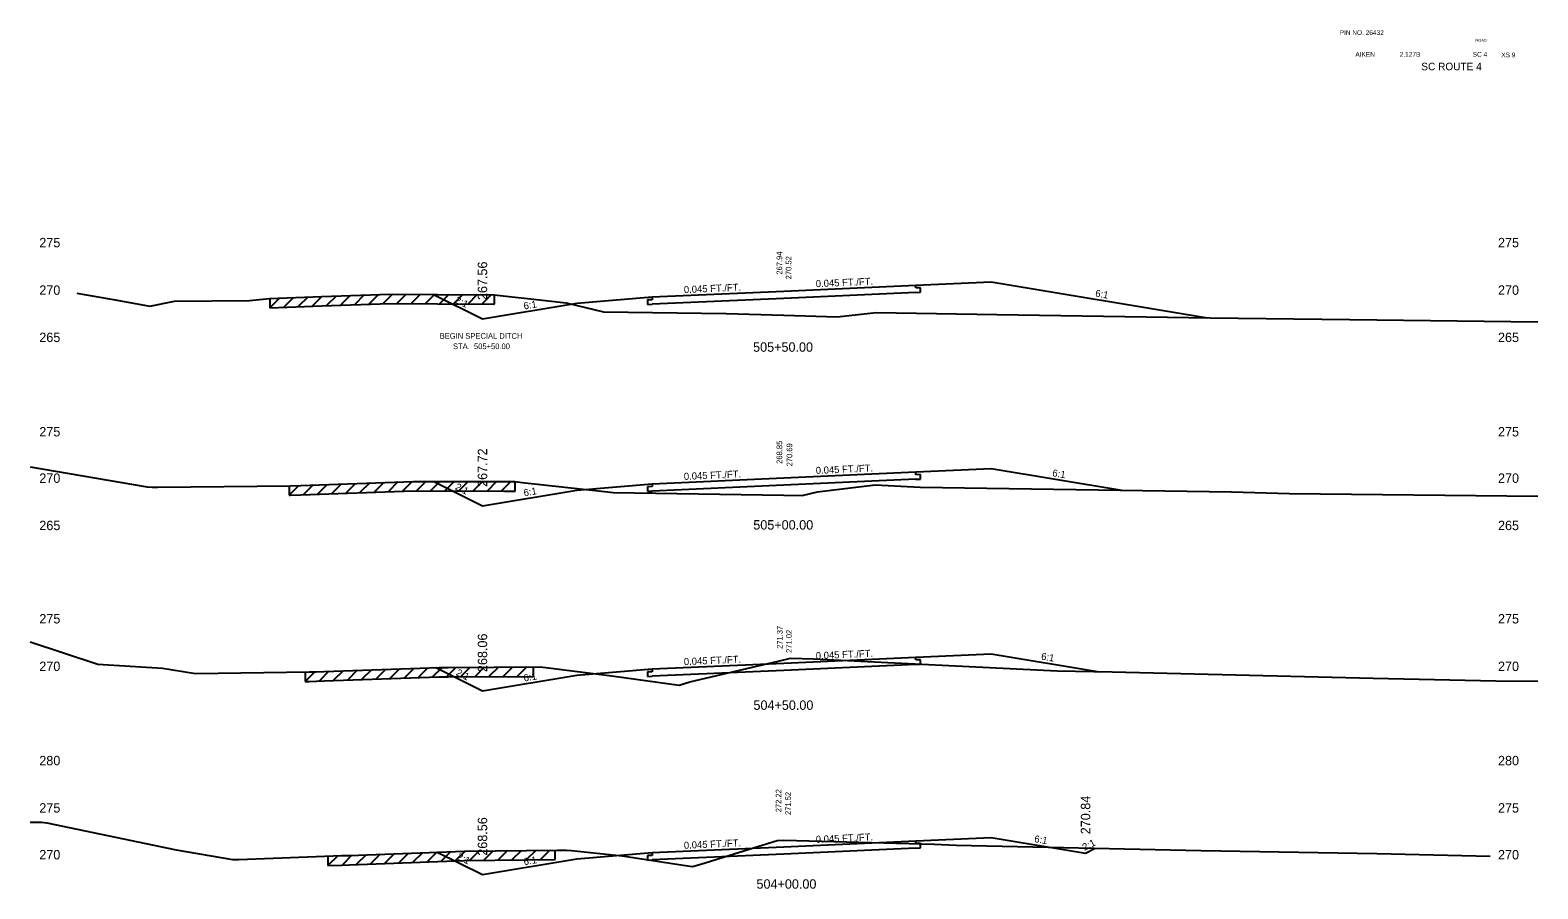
# Model space of a CAD drawing. Extents: x 883 to 1160, y 1002 to 4323.
# Drawn here: x 1000 to 1160, y 1932 to 2023.2 of the extents above; entities that cross this region are included whole.
import ezdxf

# ---------------------------------------------------------------- set-up
doc = ezdxf.new("R2010")
doc.units = 0
for name, color, linetype in [('Level 1', 7, 'Continuous'), ('Level 10', 7, 'Continuous'), ('Level 11', 7, 'Continuous'), ('Level 12', 7, 'Continuous'), ('Level 3', 7, 'Continuous'), ('Level 32', 7, 'Continuous'), ('Level 33', 7, 'Continuous'), ('Level 59', 7, 'Continuous'), ('Level 6', 7, 'Continuous'), ('Level 60', 7, 'Continuous'), ('Level 61', 7, 'Continuous'), ('Level 7', 7, 'Continuous')]:
    doc.layers.add(name, color=color, linetype=linetype)

msp = doc.modelspace()

# ---------------------------------------------------------------- linework, layer by layer
at = {"layer": 'Level 11'}
for p, q in [((1094, 1995.85), (1094, 1996.15)), ((1094.5, 1995.87), (1094, 1995.85)), ((1094, 1995.37), (1094.5, 1995.39)), ((1094.5, 1995.39), (1094.5, 1995.87)), ((1066, 1994.59), (1065.5, 1994.57)), ((1065.5, 1994.57), (1065.5, 1994.09)), ((1065.5, 1994.09), (1066, 1994.11)), ((1066, 1994.89), (1066, 1994.59)), ((1094, 1976.02), (1094, 1976.32)), ((1094.5, 1976.04), (1094, 1976.02)), ((1094.5, 1975.56), (1094.5, 1976.04)), ((1066, 1974.76), (1065.5, 1974.74)), ((1065.5, 1974.74), (1065.5, 1974.26)), ((1066, 1975.06), (1066, 1974.76)), ((1094, 1975.54), (1094.5, 1975.56)), ((1065.5, 1974.26), (1066, 1974.28)), ((1066, 1955.39), (1066, 1955.09)), ((1094, 1956.35), (1094, 1956.65)), ((1094.5, 1956.37), (1094, 1956.35)), ((1094, 1955.87), (1094.5, 1955.89)), ((1094.5, 1955.89), (1094.5, 1956.37)), ((1066, 1955.09), (1065.5, 1955.07)), ((1065.5, 1955.07), (1065.5, 1954.59)), ((1065.5, 1954.59), (1066, 1954.61)), ((1094, 1936.85), (1094, 1937.15)), ((1094.5, 1936.87), (1094, 1936.85)), ((1094, 1936.37), (1094.5, 1936.39)), ((1094.5, 1936.39), (1094.5, 1936.87)), ((1066, 1935.59), (1065.5, 1935.57)), ((1065.5, 1935.57), (1065.5, 1935.09)), ((1065.5, 1935.09), (1066, 1935.11)), ((1066, 1935.89), (1066, 1935.59))]:
    msp.add_line(p, q, dxfattribs=at)
at = {"layer": 'Level 12'}
for p, q in [((1094, 1995.37), (1080, 1994.74)), ((1080, 1994.74), (1066, 1994.11)), ((1080, 1974.91), (1066, 1974.28)), ((1094, 1975.54), (1080, 1974.91)), ((1080, 1955.24), (1066, 1954.61)), ((1094, 1955.87), (1080, 1955.24)), ((1094, 1936.37), (1080, 1935.74)), ((1080, 1935.74), (1066, 1935.11))]:
    msp.add_line(p, q, dxfattribs=at)
at = {"layer": 'Level 59'}
for p, q in [((1066, 1994.89), (1080, 1995.52)), ((1080, 1995.52), (1094, 1996.15)), ((1080, 1975.69), (1094, 1976.32)), ((1066, 1975.06), (1080, 1975.69)), ((1066, 1955.39), (1080, 1956.02)), ((1080, 1956.02), (1094, 1956.65)), ((1066, 1935.89), (1080, 1936.52)), ((1080, 1936.52), (1094, 1937.15))]:
    msp.add_line(p, q, dxfattribs=at)
at = {"layer": 'Level 6'}
for p, q in [((1094, 1996.15), (1102, 1996.51)), ((1058, 1994.22), (1066, 1994.89)), ((1094, 1976.32), (1102, 1976.68)), ((1058, 1974.39), (1066, 1975.06)), ((1094, 1956.65), (1102, 1957.01)), ((1058, 1954.72), (1066, 1955.39)), ((1094, 1937.15), (1102, 1937.51)), ((1058, 1935.22), (1066, 1935.89))]:
    msp.add_line(p, q, dxfattribs=at)
at = {"layer": 'Level 60'}
for p, q in [((1004.95, 1995.29), (1009.02, 1994.59)), ((1009.02, 1994.59), (1012.7, 1993.9)), ((1012.7, 1993.9), (1015.32, 1994.44)), ((1015.32, 1994.44), (1023.28, 1994.51)), ((1023.28, 1994.51), (1025.39, 1994.73)), ((1025.39, 1994.73), (1030.97, 1994.94)), ((1030.97, 1994.94), (1038.17, 1995.2)), ((1038.17, 1995.2), (1043.24, 1995.15)), ((1043.24, 1995.15), (1049.23, 1995.13)), ((1049.23, 1995.13), (1054.7, 1994.53)), ((1054.7, 1994.53), (1056.87, 1994.25)), ((1056.87, 1994.25), (1060.86, 1993.31)), ((1060.86, 1993.31), (1073.88, 1993.13)), ((1073.88, 1993.13), (1080, 1992.94)), ((1080, 1992.94), (1085.64, 1992.77)), ((1085.64, 1992.77), (1089.77, 1993.24)), ((1089.77, 1993.24), (1102.57, 1993.04)), ((1102.57, 1993.04), (1125.21, 1992.68)), ((1125.21, 1992.68), (1140.06, 1992.48)), ((1140.06, 1992.48), (1160, 1992.25)), ((1000, 1976.86), (1012.41, 1974.74)), ((1012.41, 1974.74), (1012.95, 1974.7)), ((1012.95, 1974.7), (1013.55, 1974.71)), ((1013.55, 1974.71), (1027.58, 1974.84)), ((1027.58, 1974.84), (1028.71, 1974.88)), ((1028.71, 1974.88), (1040.66, 1975.31)), ((1040.66, 1975.31), (1050.35, 1975.28)), ((1050.35, 1975.28), (1051.45, 1975.28)), ((1051.45, 1975.28), (1052.2, 1975.19)), ((1052.2, 1975.19), (1060.94, 1974.23)), ((1083.57, 1974.21), (1089.69, 1974.93)), ((1089.69, 1974.93), (1094.46, 1974.7)), ((1094.46, 1974.7), (1127.49, 1974.19)), ((1060.94, 1974.23), (1061.86, 1974.11)), ((1061.86, 1974.11), (1080, 1973.85)), ((1080, 1973.85), (1081.93, 1973.82)), ((1081.93, 1973.82), (1083.57, 1974.21)), ((1127.49, 1974.19), (1133.63, 1974.03)), ((1133.63, 1974.03), (1160, 1973.73)), ((1000, 1958.28), (1007.17, 1955.91)), ((1007.17, 1955.91), (1014.06, 1955.48)), ((1014.06, 1955.48), (1017.55, 1954.92)), ((1031.2, 1955.13), (1043.41, 1955.54)), ((1043.41, 1955.54), (1044.35, 1955.55)), ((1044.35, 1955.55), (1054.14, 1955.61)), ((1054.14, 1955.61), (1054.74, 1955.54)), ((1054.74, 1955.54), (1061.18, 1954.73)), ((1070, 1954.03), (1080, 1956.37)), ((1080, 1956.37), (1080.68, 1956.53)), ((1080.68, 1956.53), (1083.14, 1956.46)), ((1083.14, 1956.46), (1108.98, 1955.19)), ((1017.55, 1954.92), (1029.61, 1955.07)), ((1029.61, 1955.07), (1030.35, 1955.1)), ((1030.35, 1955.1), (1031.2, 1955.13)), ((1061.18, 1954.73), (1061.98, 1954.61)), ((1061.98, 1954.61), (1068.87, 1953.68)), ((1068.87, 1953.68), (1070, 1954.03)), ((1108.98, 1955.19), (1114.84, 1955.07)), ((1114.84, 1955.07), (1142.54, 1954.42)), ((1142.54, 1954.42), (1155.53, 1954.12)), ((1155.53, 1954.12), (1160, 1954.11)), ((1000, 1939.12), (1001.19, 1939.12)), ((1001.19, 1939.12), (1001.76, 1939.07)), ((1001.76, 1939.07), (1015.49, 1936.19)), ((1015.49, 1936.19), (1021.48, 1935.15)), ((1033.89, 1935.6), (1046.09, 1936.06)), ((1046.09, 1936.06), (1055.98, 1936.15)), ((1055.98, 1936.15), (1056.91, 1936.16)), ((1056.91, 1936.16), (1057.44, 1936.11)), ((1057.44, 1936.11), (1062.82, 1935.54)), ((1071.18, 1934.66), (1079.26, 1937.16)), ((1079.26, 1937.16), (1080, 1937.22)), ((1080, 1937.22), (1095.92, 1936.8)), ((1095.92, 1936.8), (1098.27, 1936.67)), ((1098.27, 1936.67), (1124.27, 1936.11)), ((1124.27, 1936.11), (1142.92, 1935.8)), ((1021.48, 1935.15), (1022.13, 1935.15)), ((1022.13, 1935.15), (1033.06, 1935.57)), ((1033.06, 1935.57), (1033.89, 1935.6)), ((1062.82, 1935.54), (1069.55, 1934.52)), ((1069.55, 1934.52), (1070.3, 1934.43)), ((1070.3, 1934.43), (1071.18, 1934.66)), ((1142.92, 1935.8), (1154.93, 1935.53))]:
    msp.add_line(p, q, dxfattribs=at)
at = {"layer": 'Level 61'}
for p, q in [((1026.46, 1994.77), (1025.42, 1993.73)), ((1025.42, 1994.73), (1025.42, 1993.73)), ((1025.42, 1993.73), (1030.97, 1993.94)), ((1027.96, 1994.83), (1026.92, 1993.79)), ((1029.46, 1994.88), (1028.42, 1993.84)), ((1030.96, 1994.94), (1029.92, 1993.9)), ((1030.97, 1993.94), (1038.17, 1994.2)), ((1032.46, 1994.99), (1031.42, 1993.95)), ((1033.96, 1995.04), (1032.93, 1994.01)), ((1035.46, 1995.1), (1034.43, 1994.06)), ((1036.97, 1995.15), (1035.93, 1994.12)), ((1038.45, 1995.19), (1037.43, 1994.17)), ((1038.17, 1994.2), (1043.24, 1994.15)), ((1039.92, 1995.18), (1038.93, 1994.19)), ((1041.42, 1995.17), (1040.43, 1994.18)), ((1042.92, 1995.15), (1041.93, 1994.16)), ((1043.24, 1994.15), (1049.23, 1994.13)), ((1044.43, 1995.15), (1043.43, 1994.15)), ((1045.93, 1995.14), (1044.93, 1994.15)), ((1047.43, 1995.14), (1046.43, 1994.14)), ((1048.93, 1995.13), (1047.94, 1994.13)), ((1049.23, 1994.13), (1049.28, 1994.13)), ((1049.28, 1994.13), (1049.28, 1995.13)), ((1028.52, 1974.87), (1027.49, 1973.84)), ((1027.49, 1974.84), (1027.49, 1973.84)), ((1030.03, 1974.93), (1028.99, 1973.89)), ((1031.53, 1974.98), (1030.49, 1973.94)), ((1033.03, 1975.03), (1031.99, 1974)), ((1034.53, 1975.09), (1033.49, 1974.05)), ((1036.03, 1975.14), (1034.99, 1974.11)), ((1037.53, 1975.2), (1036.49, 1974.16)), ((1039.03, 1975.25), (1038, 1974.21)), ((1040.53, 1975.31), (1039.5, 1974.27)), ((1041.99, 1975.31), (1041, 1974.31)), ((1043.49, 1975.3), (1042.5, 1974.3)), ((1044.99, 1975.29), (1044, 1974.3)), ((1046.49, 1975.29), (1045.5, 1974.29)), ((1048, 1975.28), (1047, 1974.29)), ((1049.5, 1975.28), (1048.5, 1974.28)), ((1051, 1975.28), (1050, 1974.28)), ((1051.47, 1974.28), (1051.47, 1975.28)), ((1027.49, 1973.84), (1027.58, 1973.84)), ((1027.58, 1973.84), (1028.71, 1973.88)), ((1028.71, 1973.88), (1040.66, 1974.31)), ((1040.66, 1974.31), (1050.35, 1974.28)), ((1050.35, 1974.28), (1051.45, 1974.28)), ((1051.45, 1974.28), (1051.47, 1974.28)), ((1034.71, 1955.25), (1033.67, 1954.21)), ((1036.21, 1955.3), (1035.18, 1954.27)), ((1037.71, 1955.35), (1036.68, 1954.32)), ((1039.21, 1955.4), (1038.18, 1954.37)), ((1040.72, 1955.45), (1039.68, 1954.42)), ((1042.22, 1955.5), (1041.18, 1954.47)), ((1043.71, 1955.55), (1042.68, 1954.52)), ((1045.19, 1955.56), (1044.18, 1954.55)), ((1046.69, 1955.57), (1045.68, 1954.56)), ((1048.19, 1955.57), (1047.19, 1954.57)), ((1049.69, 1955.58), (1048.69, 1954.58)), ((1051.19, 1955.59), (1050.19, 1954.58)), ((1052.7, 1955.6), (1051.69, 1954.59)), ((1053.4, 1954.6), (1053.4, 1955.6)), ((1030.2, 1955.09), (1029.17, 1954.07)), ((1029.17, 1955.07), (1029.17, 1954.07)), ((1029.17, 1954.07), (1029.61, 1954.07)), ((1029.61, 1954.07), (1030.35, 1954.1)), ((1030.35, 1954.1), (1031.2, 1954.13)), ((1031.71, 1955.15), (1030.67, 1954.11)), ((1031.2, 1954.13), (1043.41, 1954.54)), ((1033.21, 1955.2), (1032.17, 1954.16)), ((1043.41, 1954.54), (1044.35, 1954.55)), ((1044.35, 1954.55), (1053.4, 1954.6)), ((1044.66, 1936.01), (1043.62, 1934.97)), ((1046.16, 1936.06), (1045.12, 1935.02)), ((1047.64, 1936.07), (1046.63, 1935.07)), ((1049.14, 1936.09), (1048.13, 1935.08)), ((1050.64, 1936.1), (1049.63, 1935.09)), ((1052.15, 1936.11), (1051.13, 1935.11)), ((1053.65, 1936.13), (1052.64, 1935.12)), ((1055.15, 1936.14), (1054.14, 1935.13)), ((1055.71, 1935.15), (1055.71, 1936.15)), ((1032.65, 1935.55), (1031.6, 1934.51)), ((1031.6, 1935.51), (1031.6, 1934.51)), ((1031.6, 1934.51), (1033.06, 1934.57)), ((1033.06, 1934.57), (1033.89, 1934.6)), ((1034.15, 1935.61), (1033.11, 1934.57)), ((1033.89, 1934.6), (1046.09, 1935.06)), ((1035.65, 1935.67), (1034.61, 1934.63)), ((1037.15, 1935.73), (1036.11, 1934.69)), ((1038.65, 1935.78), (1037.61, 1934.74)), ((1040.16, 1935.84), (1039.12, 1934.8)), ((1041.66, 1935.89), (1040.62, 1934.86)), ((1043.16, 1935.95), (1042.12, 1934.91)), ((1046.09, 1935.06), (1055.71, 1935.15))]:
    msp.add_line(p, q, dxfattribs=at)
at = {"layer": 'Level 7'}
for p, q in [((1102, 1996.51), (1124.95, 1992.69)), ((1042.8, 1995.16), (1048, 1992.56)), ((1048, 1992.56), (1058, 1994.22)), ((1102, 1976.68), (1115.85, 1974.37)), ((1042.84, 1975.3), (1048, 1972.72)), ((1048, 1972.72), (1058, 1974.39)), ((1102, 1957.01), (1113.47, 1955.1)), ((1043.05, 1955.53), (1048, 1953.06)), ((1048, 1953.06), (1058, 1954.72)), ((1102, 1937.51), (1112, 1935.84)), ((1112, 1935.84), (1113.01, 1936.35)), ((1043.21, 1935.95), (1048, 1933.56)), ((1048, 1933.56), (1058, 1935.22))]:
    msp.add_line(p, q, dxfattribs=at)

# ---------------------------------------------------------------- texts
at = {"layer": 'Level 1'}
for s, height, p in [('PIN NO. 26432', 0.5, (1138.97, 2022.71)), ('AIKEN', 0.5, (1140.64, 2020.4)), (' 2.127B', 0.5, (1145.15, 2020.4)), ('SC 4', 0.5, (1153.09, 2020.4)), ('XS 9', 0.5, (1156.12, 2020.34)), ('SC ROUTE 4', 0.8, (1147.63, 2018.96)), ('505+50.00', 1, (1076.72, 1989.07)), ('505+00.00', 1, (1076.74, 1970.19)), ('504+50.00', 1, (1076.76, 1951.05)), ('504+00.00', 1, (1077.08, 1932.06))]:
    msp.add_text(s, height=height, dxfattribs=at).set_placement(p)
at = {"layer": 'Level 10'}
for s, p in [('267.94', (1079.81, 1997.26)), ('268.85', (1079.81, 1977.17)), ('271.37', (1079.85, 1957.52)), ('272.22', (1079.72, 1940.17))]:
    msp.add_text(s, height=0.6, rotation=90, dxfattribs=at).set_placement(p)
at = {"layer": 'Level 3'}
for s, height, p in [('ROAD', 0.3, (1153.38, 2021.99)), (' 275', 1, (1000.6, 2000.16)), (' 275', 1, (1155.4, 2000.16)), (' 270', 1, (1000.6, 1995.12)), (' 270', 1, (1155.4, 1995.12)), (' 265', 1, (1000.6, 1990.1)), (' 265', 1, (1155.4, 1990.1)), (' 275', 1, (1000.6, 1980.08)), (' 275', 1, (1155.4, 1980.08)), (' 270', 1, (1000.6, 1975.15)), (' 270', 1, (1155.4, 1975.15)), (' 265', 1, (1000.6, 1970.13)), (' 265', 1, (1155.4, 1970.13)), (' 275', 1, (1000.6, 1960.22)), (' 275', 1, (1155.4, 1960.22)), (' 270', 1, (1000.6, 1955.17)), (' 270', 1, (1155.4, 1955.17)), (' 280', 1, (1000.6, 1945.16)), (' 280', 1, (1155.4, 1945.16)), (' 275', 1, (1000.6, 1940.14)), (' 275', 1, (1155.4, 1940.14)), (' 270', 1, (1000.6, 1935.17)), (' 270', 1, (1155.4, 1935.17))]:
    msp.add_text(s, height=height, dxfattribs=at).set_placement(p)
at = {"layer": 'Level 32'}
for s, rotation, p in [('0.045 FT./FT.', 2.5766, (1083.39, 1995.92)), ('0.045 FT./FT.', 2.5766, (1069.39, 1995.29)), ('6:1', 350.5377, (1112.99, 1994.93)), ('2:1', 333.435, (1045.01, 1994.33)), ('6:1', 9.4623, (1052.43, 1993.55)), ('0.045 FT./FT.', 2.5766, (1069.39, 1975.46)), ('0.045 FT./FT.', 2.5766, (1083.39, 1976.09)), ('6:1', 350.5377, (1108.44, 1975.86)), ('2:1', 333.435, (1045.03, 1974.49)), ('6:1', 9.4623, (1052.43, 1973.72)), ('0.045 FT./FT.', 2.5766, (1069.39, 1955.79)), ('0.045 FT./FT.', 2.5766, (1083.39, 1956.42)), ('6:1', 350.5377, (1107.25, 1956.39)), ('2:1', 333.435, (1045.13, 1954.77)), ('6:1', 9.4623, (1052.43, 1954.05)), ('0.045 FT./FT.', 2.5766, (1083.39, 1936.92)), ('6:1', 350.5377, (1106.52, 1937.01)), ('0.045 FT./FT.', 2.5766, (1069.39, 1936.29)), ('2:1', 26.5651, (1111.89, 1936.07)), ('2:1', 333.435, (1045.21, 1935.23)), ('6:1', 9.4623, (1052.43, 1934.55))]:
    msp.add_text(s, height=0.75, rotation=rotation, dxfattribs=at).set_placement(p)
for s, p in [('BEGIN SPECIAL DITCH', (1043.46, 1990.45)), ('STA.  505+50.00', (1044.87, 1989.35))]:
    msp.add_text(s, height=0.6, dxfattribs=at).set_placement(p)
at = {"layer": 'Level 33'}
for s, p in [('267.56', (1048.5, 1994.56)), ('267.72', (1048.5, 1974.72)), ('268.06', (1048.5, 1955.06)), ('270.84', (1112.5, 1937.84)), ('268.56', (1048.5, 1935.56))]:
    msp.add_text(s, height=1, rotation=90, dxfattribs=at).set_placement(p)
at = {"layer": 'Level 59'}
for s, p in [(' 270.52', (1080.79, 1996.54)), (' 270.69', (1080.88, 1976.68)), (' 271.02', (1080.83, 1956.87)), (' 271.52', (1080.73, 1939.66))]:
    msp.add_text(s, height=0.6, rotation=90, dxfattribs=at).set_placement(p)

doc.saveas('drawing.dxf')
